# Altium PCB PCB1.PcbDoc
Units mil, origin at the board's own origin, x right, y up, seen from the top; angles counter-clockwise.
Board outline 2045 x 750 mil, 2 copper layers (Top Layer, Bottom Layer); 49 components, 40 nets, 164 pads, 21 vias.
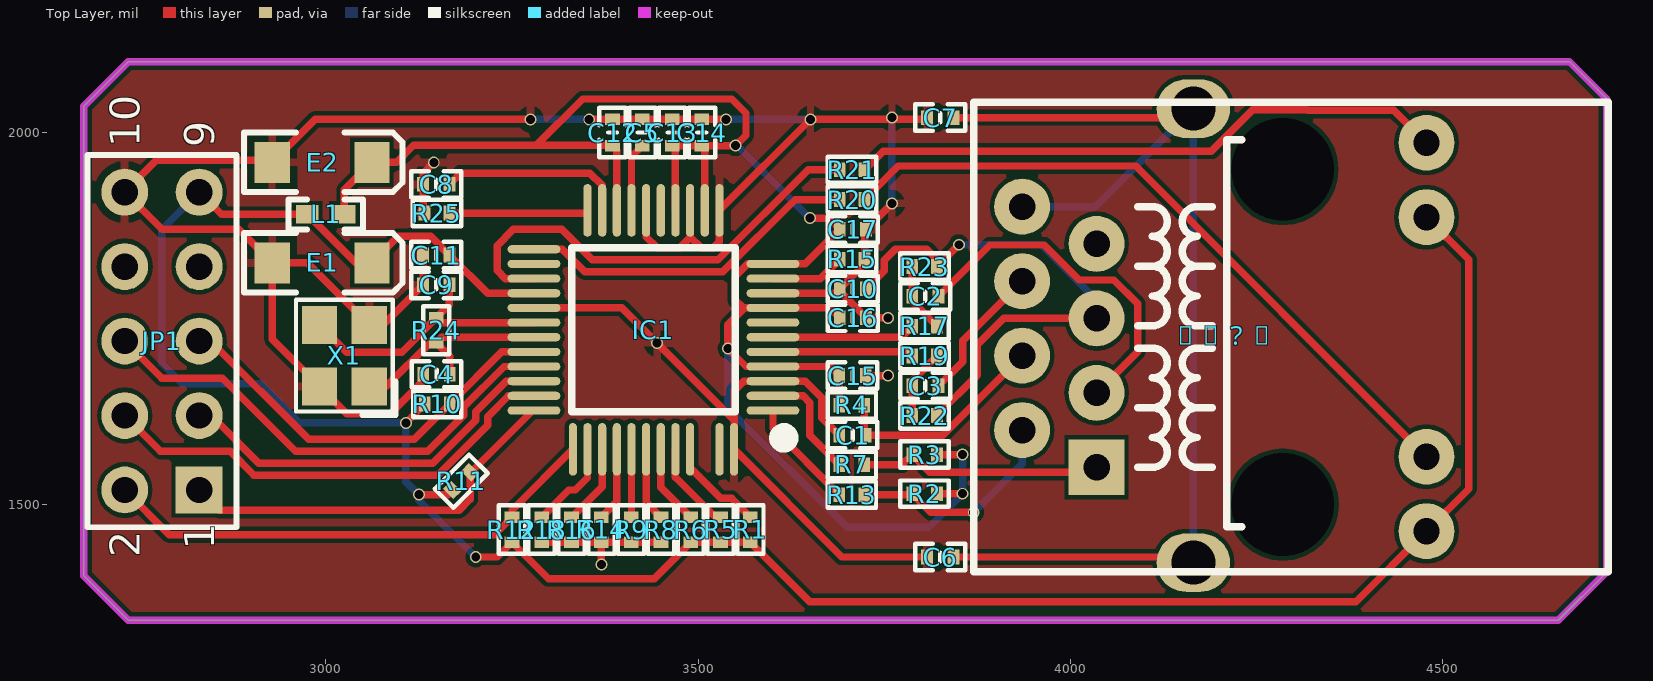
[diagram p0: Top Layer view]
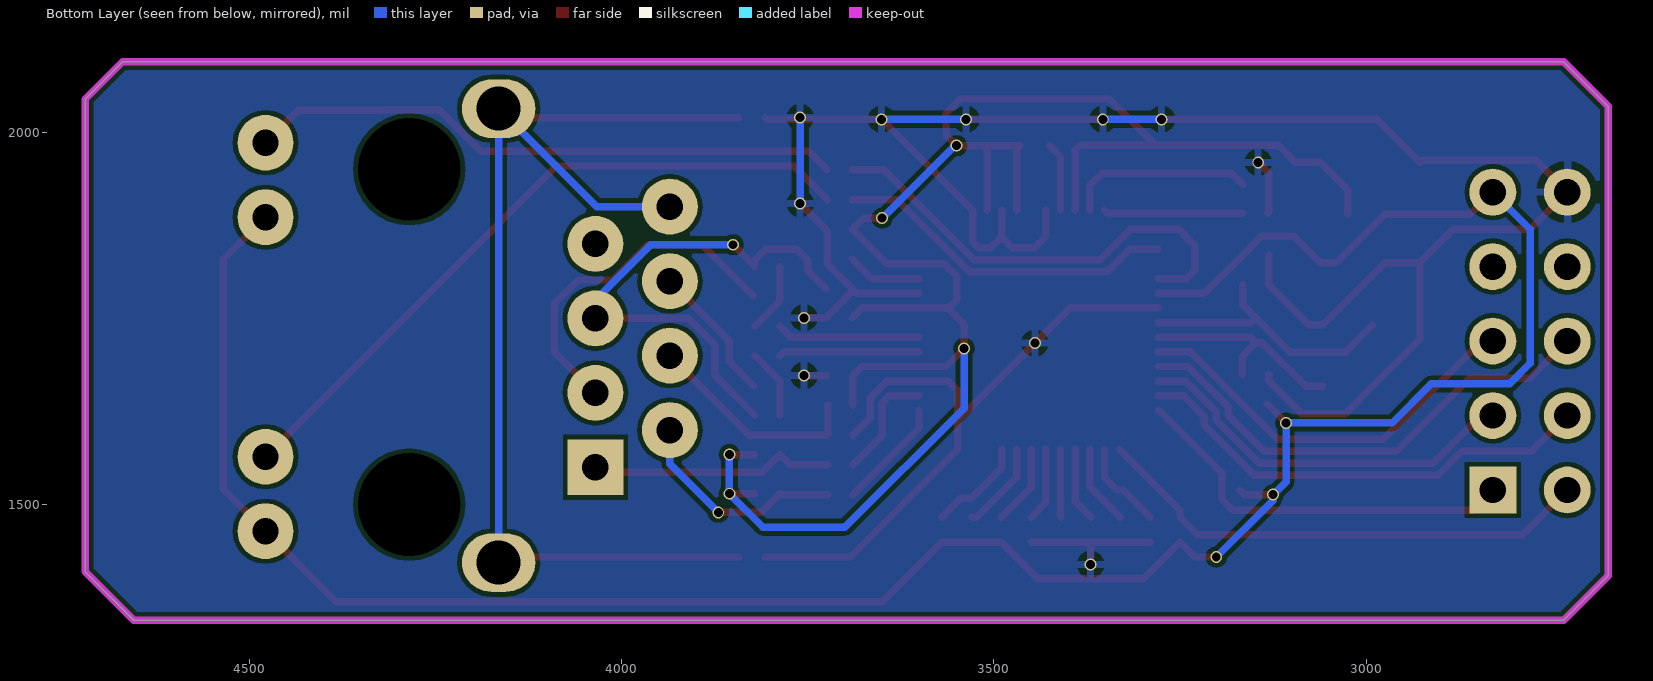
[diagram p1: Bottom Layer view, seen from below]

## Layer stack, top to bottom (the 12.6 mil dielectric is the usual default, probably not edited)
Top Solder: solder mask 0.4, Solder Resist, Dk 3.5
Top Layer: signal copper 1.4
Dielectric 1: dielectric 12.6, FR-4, Dk 4.8
Bottom Layer: signal copper 1.4
Bottom Solder: solder mask 0.4, Solder Resist, Dk 3.5

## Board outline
2675,1405 2735,1345 4655,1345 4720,1410 4720,2045 4670,2095 2735,2095 2675,2035

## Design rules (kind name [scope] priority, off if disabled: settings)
Clearance [All] p1: gap=6 ignorepadtopadclearanceinfootprint=FALSE
PolygonConnect [All] p1: connectstyle=Relief reliefconductorwidth=10 reliefentries=4 polygonreliefangle="90 Angle" airgapwidth=10
RoutingVias [All] p1: holewidth=28 width=50 viastyle="Through Hole" minholewidth=28 minwidth=50 maxholewidth=28 maxwidth=50
SolderMaskExpansion [All] p1: expansion=4
Width [All] p1: maxlimit=100 minlimit=6 preferedwidth=10
30 further rules are at their usual default settings.

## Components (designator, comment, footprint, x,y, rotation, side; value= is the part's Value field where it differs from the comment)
C1 "22nF" "C 0402_L" 3707.28,1593.66 r180 top
C2 "6.8nF" "C 0402_L" 3805,1780 r180 top
C3 "6.8nF" "C 0402_L" 3805,1660 r180 top
C4 "18pF" "C 0402_L" 3148.73,1675.46 r0 top
C5 "4.7uF" "C 0402_L" 3425,2000 r90 top
C6 "100nF" "C 0402_L" 3825,1430 r0 top
C7 "100nF" "C 0402_L" 3825,2020 r0 top
C8 "10nF" "C 0402_L" 3148.31,1930.46 r180 top
C9 "18pF" "C 0402_L" 3148.31,1795.46 r0 top
C10 "10nF" "C 0402_L" 3707.71,1790 r180 top
C11 "100nF" "C 0402_L" 3148.31,1835.45 r0 top
C12 "100nF" "C 0402_L" 3385,2000 r90 top
C13 "100nF" "C 0402_L" 3465,2000 r90 top
C14 "100nF" "C 0402_L" 3505,2000 r90 top
C15 "100nF" "C 0402_L" 3707.28,1673.66 r0 top
C16 "100nF" "C 0402_L" 3707.71,1751.18 r0 top
C17 "100nF" "C 0402_L" 3707.71,1870 r0 top
E1 "10uF/16V" "CD A(3216)" 2995,1825 r180 top
E2 "10uF/16V" "CD A(3216)" 2995,1960 r180 top
IC1 "W5500" LQFP48-7*7 3440,1735 r90 top
JP1 "Header 5X2" HDR2.54-LI-2x5P 2780,1720 r90 top
L1 "120" "L 0402" 3000,1890 r0 top
R1 "10K" "R 0402_L" 3570,1467.71 r270 top
R2 "49R9 1%" "R 0402_L" 3803.04,1515 r0 top
R3 "49R9 1%" "R 0402_L" 3803.04,1567.5 r0 top
R4 "10 1%" "R 0402_L" 3707.28,1633.66 r180 top
R5 "10K" "R 0402_L" 3530,1467.71 r270 top
R6 "10K" "R 0402_L" 3490,1467.71 r270 top
R7 "0R" "R 0402_L" 3707.28,1553.66 r180 top
R8 "10K" "R 0402_L" 3450,1467.71 r270 top
R9 "10K" "R 0402_L" 3410,1467.71 r270 top
R10 "10K" "R 0402_L" 3150.69,1635.46 r180 top
R11 "10K" "R 0402_L" 3182.53,1532.52 r225 top
R12 "10K" "R 0402_L" 3250,1467.71 r270 top
R13 "0R" "R 0402_L" 3707.28,1513.66 r180 top
R14 "10K" "R 0402_L" 3370,1467.71 r270 top
R15 "12.4K 1%" "R 0402_L" 3707.71,1830 r180 top
R16 "10K" "R 0402_L" 3330,1467.71 r270 top
R17 "0R" "R 0402_L" 3805,1740 r180 top
R18 "10K" "R 0402_L" 3289.85,1467.71 r270 top
R19 "0R" "R 0402_L" 3805,1700 r180 top
R20 "330" "R 0402_L" 3707.71,1910 r180 top
R21 "330" "R 0402_L" 3707.71,1950 r180 top
R22 "82 1%" "R 0402_L" 3803.04,1620 r0 top
R23 "82 1%" "R 0402_L" 3805,1820 r180 top
R24 "1M" "R 0402_L" 3148.31,1735.45 r270 top
R25 "10K" "R 0402_L" 3148.31,1891.87 r0 top
RJ？1 "HR911105A" RJ-45A12 4285,1725.45 r90 top
X1 "25M" "OSC 3225-4P" 3025,1700.45 r90 top

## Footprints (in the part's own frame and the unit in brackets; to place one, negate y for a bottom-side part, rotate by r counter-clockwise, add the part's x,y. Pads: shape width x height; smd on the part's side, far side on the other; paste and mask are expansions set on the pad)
"C 0402_L" [mm] "无极性贴片电容         淘宝ID:黄晶宝石"
  rect 0.4x0.5 smd: 1(-0.45,0) 2(0.45,0)
  silkscreen extent -0.85,-0.45 0.85,0.45, body extent -0.5,-0.26 0.5,0.26, height 0.53
"CD A(3216)" [mm] "长3.2mm，宽1.6mm，厚1.6mm      淘宝ID:黄晶宝石"
  rect 1.2x1.4 smd: 1(-1.7,0) 2(1.7,0)
  silkscreen extent -2.74,-1.02 2.67,1.02, body extent -1.6,-0.8 1.6,0.8, height 1.6
HDR2.54-LI-2x5P [mm] "双排排针，5x2脚 淘宝ID:黄晶宝石   店铺网址:https://shop463601444.taobao.com"
  rect 1.6x1.6 hole 0.9: 1(-5.08,-1.27)
  round 1.6 hole 0.9: 2(-5.08,1.27) 3(-2.54,-1.27) 4(-2.54,1.27) 5(0,-1.27) 6(0,1.27) 7(2.54,-1.27) 8(2.54,1.27) 9(5.08,-1.27) 10(5.08,1.27)
  silkscreen extent -6.35,-2.54 6.35,2.54, body extent -6.35,-2.54 6.35,2.54, height 8.5
"L 0402" [mil] "小功率贴片电感        淘宝ID:黄晶宝石"
  rect 30x25 smd: 1(-25,0) 2(25,0)
  silkscreen extent -50,-20 50,20, body extent -20,-10 20,10, height 20
LQFP48-7*7 [mm] "7x7mm，0.5mm        淘宝ID:黄晶宝石"
  oval 0.279x1.8 smd: 1(-2.75,-4.075) 2(-2.25,-4.075) 3(-1.75,-4.075) 4(-1.25,-4.075) 5(-0.75,-4.075) 6(-0.25,-4.075) 7(0.25,-4.075) 8(0.75,-4.075) 9(1.25,-4.075) 10(1.75,-4.075) 11(2.25,-4.075) 25(2.75,4.075) 26(2.25,4.075) 27(1.75,4.075) 28(1.25,4.075) 29(0.75,4.075) 30(0.25,4.075) 31(-0.25,4.075) 32(-0.75,4.075) 33(-1.25,4.075) 34(-1.75,4.075) 35(-2.25,4.075) 36(-2.75,4.075)
  oval 1.8x0.279 smd: 14(4.075,-2.25) 15(4.075,-1.75) 16(4.075,-1.25) 17(4.075,-0.75) 18(4.075,-0.25) 19(4.075,0.25) 20(4.075,0.75) 21(4.075,1.25) 22(4.075,1.75) 23(4.075,2.25) 37(-4.075,2.75) 38(-4.075,2.25) 39(-4.075,1.75) 40(-4.075,1.25) 41(-4.075,0.75) 42(-4.075,0.25) 43(-4.075,-0.25) 44(-4.075,-0.75) 45(-4.075,-1.25) 47(-4.075,-2.25) 48(-4.075,-2.75)
  silkscreen extent -3.93,-4.69 2.79,2.79, body extent -4.5,-4.5 4.5,4.5, height 1.45
"OSC 3225-4P" [mm] "3.2*2.5*0.7mm(长宽高)                         淘宝ID:黄晶宝石"
  rect 1.3x1.2 smd: 1(-1.05,-0.85) 2(1.05,-0.85) 3(1.05,0.85) 4(-1.05,0.85)
  silkscreen extent -2.03,-1.75 1.91,1.65, body extent -1.6,-1.25 1.6,1.25, height 0.7
"R 0402_L" [mm] "1/16W贴片电阻     淘宝ID:黄晶宝石"
  rect 0.4x0.5 smd: 1(-0.4,0) 2(0.45,0)
  silkscreen extent -0.8,-0.45 0.85,0.45, body extent -0.5,-0.25 0.5,0.25, height 0.3
RJ-45A12 [mm] "网线接口"
  oval 2x2.5 hole 1.5: 0(-7.695,3.05) 0(7.785,3.05)
  round 3.302 hole 3.5: 0(-5.715,0) 0(5.715,0)
  rect 1.905x1.905 hole 0.9: 1(-4.445,6.35)
  round 1.905 hole 0.9: 2(-3.175,8.89) 3(-1.905,6.35) 4(-0.635,8.89) 5(0.635,6.35) 6(1.905,8.89) 7(3.175,6.35) 8(4.445,8.89) 9(-6.625,-4.9) 10(-4.085,-4.9) 11(4.085,-4.9) 12(6.625,-4.9)
  silkscreen extent -8,-11.1 8,10.54, body extent -7.97,-10.93 7.91,10.47, height 1.5

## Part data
C1 C2 C3 C4 C5 C6 C7 C8 C9 C10 C11 C12 C13 C14 C15 C16 C17: library part C, "贴片电容"
E1 E2: library part CT, "贴片钽电容"
IC1: "网口芯片"
JP1: "5*2P接插件"
L1: library part L, "小功率贴片电感"
R1 R2 R3 R4 R5 R6 R7 R8 R9 R10 R11 R12 R13 R14 R15 R16 R17 R18 R19 R20 R21 R22 R23 R24 R25: library part R, "贴片电阻"
RJ？1: "带灯以太网接口"
X1: library part XTAL-4P, "4脚无源晶振"

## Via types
v1: diameter 16, hole 12, Top Layer to Bottom Layer, tented both sides, 21 vias

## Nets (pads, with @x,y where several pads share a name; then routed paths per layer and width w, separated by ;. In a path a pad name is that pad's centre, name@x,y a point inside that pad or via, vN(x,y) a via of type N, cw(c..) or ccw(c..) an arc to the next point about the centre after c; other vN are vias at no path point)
3.3V: C11.2 E1.1 IC1.28 JP1.9 L1.1 R1.2 R5.2 R6.2 R10.2 R11.2 R12.2 RJ？1.9 RJ？1.11 | length 3315.8
  Top Layer w10: JP1.9 2860,1890 L1.1 3040,1825 E1.1 3097.38,1860.45 3141.02,1860.45 C11.2 3217.26,1784.21 IC1.28 ; v1(3107.52,1610) R10.2 ; v1(3125,1513.66) 3163.66,1513.66 R11.2 ; v1(3201.32,1430) 3230,1430 R12.2 3299,1401 3441,1401 R6.2 R5.2 R1.2 3650,1370 4383.29,1370 RJ？1.9 4535,1521.71 4535,1829.19 RJ？1.11
  Bottom Layer w10: JP1.9 2780,1870 2780,1690 2807.5,1662.5 2912.5,1662.5 2965,1610 v1(3107.52,1610) 3107.52,1531.14 v1(3125,1513.66) 3125,1506.32 v1(3201.32,1430)
3.3V-A: C12.1 C13.1 C14.1 C15.1 C16.1 C17.1 E2.1 IC1.4 IC1.8 IC1.11 IC1.15 IC1.17 IC1.21 L1.2 R2.2 R3.2 R4.2 | length 2538
  Top Layer w10: L1.2 3025,1923.07 E2.1 3095,1960 3117.74,1982.74 3282.74,1982.74 ; IC1.21 3390.79,1976.5 C12.1 3384.55,1982.74 3282.74,1982.74 ; IC1.17 3469.53,1977.76 C13.1 C14.1 ; IC1.15 3508.9,1978.39 C14.1 ; v1(3650,1885) 3675,1885 C17.1 3643.58,1823.58 IC1.11 3566.47,1823.58 3550,1807.12 3550,1775 3560.47,1764.53 3562.8,1764.53 ; R4.2 C15.1 3677.44,1685.79 IC1.4 3564.21,1685.79 v1(3540,1710) 3540,1741.73 3562.8,1764.53 ; C16.1 3676.65,1764.53 IC1.8 3562.8,1764.53 ; R2.2 v1(3855,1515) ; R3.2 v1(3855,1567.5) ; 3282.74,1982.74 3345,2045 3545,2045 3564.21,2025.79 3564.21,1996.5 v1(3550,1982.28) C14.1
  Bottom Layer w10: v1(3540,1710) 3540,1630 3700,1470 3810,1470 v1(3855,1515) v1(3855,1567.5) ; v1(3550,1982.28) 3552.72,1982.28 v1(3650,1885)
ACTLED: IC1.27 R21.2 | length 623.4
  Top Layer w10: IC1.27 3241.1,1803.9 3230,1815 3230,1848.11 3251.89,1870 3316.73,1870 3357.73,1829 3526.63,1829 3647.63,1950 R21.2
GND: C1.2 C4.1 C5.2 C6.1 C7.1 C8.2 C9.1 C10.2 C11.1 C12.2 C13.2 C14.2 C15.2 C16.2 C17.2 E1.2 E2.2 IC1.3 IC1.9 IC1.14 IC1.16 IC1.19 IC1.29 IC1.48 JP1.10 R8.2 R9.2 R14.2 R15.1 R16.2 R18.2 R25.1 X1.2 X1.4 | length 4088.1
  Top Layer w10: C11.1 C9.1 3076.93,1741.79 X1.2 2975.26,1825 E1.2 ; C4.1 3131.01,1666.89 3086.64,1622.52 3028.13,1622.52 X1.4 2928.07,1722.58 E1.2 ; R25.1 3130.59,1893.83 C8.2 3130.59,1945.59 v1(3145,1960) ; v1(3275,2017.71) 2985.78,2017.71 E2.2 2925.57,1962.5 2772.5,1962.5 JP1.10 2780,1870 2883.07,1870 E1.2 ; IC1.29 3397.65,1764.53 v1(3445,1717.18) 3548.27,1613.91 ; R18.2 R16.2 R14.2 ; v1(3353.7,2017.71) C12.2 C5.2 C13.2 C14.2 v1(3537.28,2017.71) ; v1(3370,1420) R14.2 ; IC1.19 3430.16,1859.68 3444.84,1845 3475,1845 3489.21,1859.21 3489.21,1859.68 ; R8.2 R9.2 R14.2 ; IC1.16 3489.21,1859.68 ; IC1.9 3684.21,1784.21 C10.2 ; C1.2 3666,1617.23 3666,1644 3643.9,1666.1 IC1.3 3561.1,1666.1 3548.27,1653.27 3548.27,1613.91 ; C15.2 v1(3755,1673.66) ; v1(3755,1751.17) C16.2 3690,1786.6 C10.2 ; v1(3760,1904.57) C17.2 3723.46,1868.03 R15.1 3723.46,1823.46 C10.2 ; C6.1 3692.82,1430 IC1.48 3548.27,1613.91 ; C7.1 3805,2017.71 v1(3650.85,2017.71) IC1.14 3528.58,1853.58 3520,1845 3503.9,1845 3489.21,1859.68
  Bottom Layer w10: v1(3275,2017.71) v1(3353.7,2017.71) ; v1(3537.28,2017.71) v1(3650.85,2017.71) ; v1(3760,1904.57) v1(3760,2020)
LINKLED: IC1.25 R20.2 | length 463.2
  Top Layer w10: IC1.25 3317.37,1843.27 3347.64,1813 3533.25,1813 3630.25,1910 R20.2
NetC1_1: C1.1 R4.1 RJ？1.4 | length 295.1
  Top Layer w10: R4.1 3723.03,1595.63 C1.1 3828.21,1593.66 RJ？1.4
NetC2_1: C2.1 RJ？1.3 | length 470.9
  Top Layer w10: C2.1 3891.67,1848.95 3964.68,1848.95 4011.68,1801.95 4058.05,1801.95 4090,1770 4090,1705.45 RJ？1.3
NetC2_2: C2.2 R17.1 R23.2 | length 93.9
  Top Layer w10: R23.2 C2.2 3787.29,1773.47 R17.1
NetC3_1: C3.1 RJ？1.6 | length 189.8
  Top Layer w10: C3.1 3855,1692.28 3855,1720.45 RJ？1.6 RJ？1.6@3935,1797.63
NetC3_2: C3.2 R19.1 R22.1 | length 93.9
  Top Layer w10: R22.1 C3.2 3787.29,1666.54 R19.1
NetC4_2: C4.2 IC1.31 R24.2 X1.1 | length 298.2
  Top Layer w10: X1.1 3081.4,1659.11 3140.02,1717.74 R24.2 ; C4.2 3166.44,1699.6 R24.2 ; IC1.31 3155.72,1725.16 R24.2
NetC5_1: C5.1 IC1.20 | length 92.9
  Top Layer w10: IC1.20 3410.47,1967.76 C5.1
NetC6_2: C6.2 C7.2 RJ？1.0@4164.92,1422.49 RJ？1.0@4164.92,2031.94 RJ？1.8 | length 1546.3
  Top Layer w10: C6.2 4157.42,1430 RJ？1.0@4164.92,1422.49 ; C7.2 4152.98,2020 RJ？1.0@4164.92,2031.94
  Bottom Layer w10: RJ？1.8 4033.43,1900.45 4164.92,2031.94 RJ？1.0@4164.92,1422.49
NetC8_1: C8.1 IC1.22 | length 251.7
  Top Layer w10: C8.1 3181.02,1945.45 3354.68,1945.45 3371.1,1929.03 IC1.22
NetC9_2: C9.2 IC1.30 R24.1 X1.3 | length 376.4
  Top Layer w10: X1.3 3028.13,1705.2 3102.3,1705.2 R24.1 ; C9.2 3166.02,1768.92 R24.1 ; IC1.30 3154.66,1744.84 R24.1
NetC10_1: C10.1 R22.2 R23.1 RJ？1.5 | length 714.5
  Top Layer w10: C10.1 3750,1814.57 3750,1828.63 3764.63,1843.27 3806.73,1843.27 3820.75,1829.25 R23.1 v1(3850,1849.26) ; R22.2 3875,1674.25 3875,1715 3910.45,1750.45 RJ？1.5
  Bottom Layer w10: v1(3850,1849.26) 3960.74,1849.26 4035,1775 RJ？1.5
NetIC1_10: IC1.10 R15.2 | length 100.4
  Top Layer w10: IC1.10 3663.9,1803.9 R15.2
NetIC1_23: IC1.23 R25.2 | length 186.9
  Top Layer w10: R25.2 3347.84,1891.87 IC1.23
NetIC1_38: IC1.38 R18.1 | length 121.6
  Top Layer w10: R18.1 3326.38,1520 3335,1520 3351.42,1536.42 IC1.38
NetIC1_39: IC1.39 R16.1 | length 108.1
  Top Layer w10: R16.1 3371.1,1524.57 IC1.39
NetIC1_40: IC1.40 R14.1 | length 99.7
  Top Layer w10: R14.1 3390.79,1504.25 IC1.40
NetIC1_41: IC1.41 R9.1 | length 91.3
  Top Layer w10: R9.1 3410.47,1483.94 IC1.41
NetIC1_42: IC1.42 R8.1 | length 99.3
  Top Layer w10: IC1.42 3430.16,1503.31 R8.1
NetIC1_43: IC1.43 R6.1 | length 107.7
  Top Layer w10: IC1.43 3449.84,1523.62 R6.1
NetIC1_44: IC1.44 R5.1 | length 120.1
  Top Layer w10: IC1.44 3469.53,1537.21 3523.27,1483.46 R5.1
NetIC1_45: IC1.45 R1.1 | length 132.9
  Top Layer w10: IC1.45 3489.21,1550.04 3530.59,1508.66 3544.8,1508.66 R1.1
NetR2_1: R2.1 R13.1 RJ？1.2 | length 295.2
  Top Layer w10: R13.1 3785.95,1513.66 R2.1 3812.28,1490 v1(3870,1490)
  Bottom Layer w10: v1(3870,1490) 3935,1555 RJ？1.2
NetR3_1: R3.1 R7.1 RJ？1.1 | length 330.4
  Top Layer w10: R7.1 3773.45,1553.66 R3.1 3811.12,1543.66 4028.21,1543.66 RJ？1.1
NetR20_1: R20.1 RJ？1.10 | length 934.8
  Top Layer w10: R20.1 3768.46,1955 4087.54,1955 RJ？1.10
NetR21_1: R21.1 RJ？1.12 | length 806
  Top Layer w10: R21.1 3748.46,1975 4189.06,1975 4244.41,2030.35 4318.1,2030.35 4318.45,2030 4434.19,2030 RJ？1.12
PB4/RSTn: IC1.37 JP1.2 R12.1 | length 679.5
  Top Layer w10: JP1.2 2790,1460 3226.54,1460 R12.1 3250,1492.82 IC1.37
PB5/INTn: IC1.36 JP1.1 R11.1 | length 538.7
  Top Layer w10: JP1.1 2857.18,1492.82 3179.26,1492.82 3193.66,1507.22 R11.1@3193.66,1542.38 ; R11.1@3193.31,1542.03 R11.1@3193.66,1542.38 ; R11.1 R11.1@3193.66,1542.38 ; IC1.36 3278.01,1626.73 R11.1@3193.66,1542.38
PB9/SCSn: IC1.32 JP1.5 R10.1 | length 552.9
  Top Layer w10: JP1.5 2845,1720 2977,1588 3118.79,1588 3166.25,1635.46 R10.1 3236.46,1705.47 IC1.32
PB13/SCLK: IC1.33 JP1.6 | length 664.7
  Top Layer w10: JP1.6 2780,1670 2861.29,1670 2959.29,1572 3137,1572 3185.32,1620.32 3185.32,1631.71 3239.4,1685.79 IC1.33
PB14/MISO: IC1.34 JP1.3 | length 528.3
  Top Layer w10: JP1.3 2846.18,1620 2910.18,1556 3143.63,1556 3201.32,1613.69 3201.32,1625.08 3242.34,1666.1 IC1.34
PB15/MOSI: IC1.35 JP1.4 | length 633.4
  Top Layer w10: JP1.4 2778,1572 2871.55,1572 2903.55,1540 3150.25,1540 3217.32,1607.06 3217.32,1618.45 3245.28,1646.42 IC1.35
RXN: IC1.5 R19.2 | length 189.1
  Top Layer w10: IC1.5 3781.82,1705.47 R19.2
RXP: IC1.6 R17.2 | length 193
  Top Layer w10: IC1.6 3772.44,1725.16 R17.2
TXN: IC1.1 R13.2 | length 150
  Top Layer w10: IC1.1 3600.45,1602.78 R13.2
TXP: IC1.2 R7.2 | length 153.4
  Top Layer w10: IC1.2 3640.96,1646.42 3650,1637.37 3650,1593.23 R7.2
pads on no net: IC1.7 IC1.18 IC1.26 IC1.47 JP1.7 JP1.8 RJ？1.0@4285,1500.45 RJ？1.0@4285,1950.45 RJ？1.7

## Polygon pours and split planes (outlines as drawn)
GND on Top Layer (solid, remove dead copper, pour order 6): 2570,2170 4845,2170 4860,2155 4860,1220 2570,1220 2550,1240
GND on Bottom Layer (solid, remove dead copper, pour order 8): 2620,2205 4825,2205 4825,1285 4780,1240 4775,1245 2615,1245

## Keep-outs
Keep-Out Layer:
  the board outline again, w10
